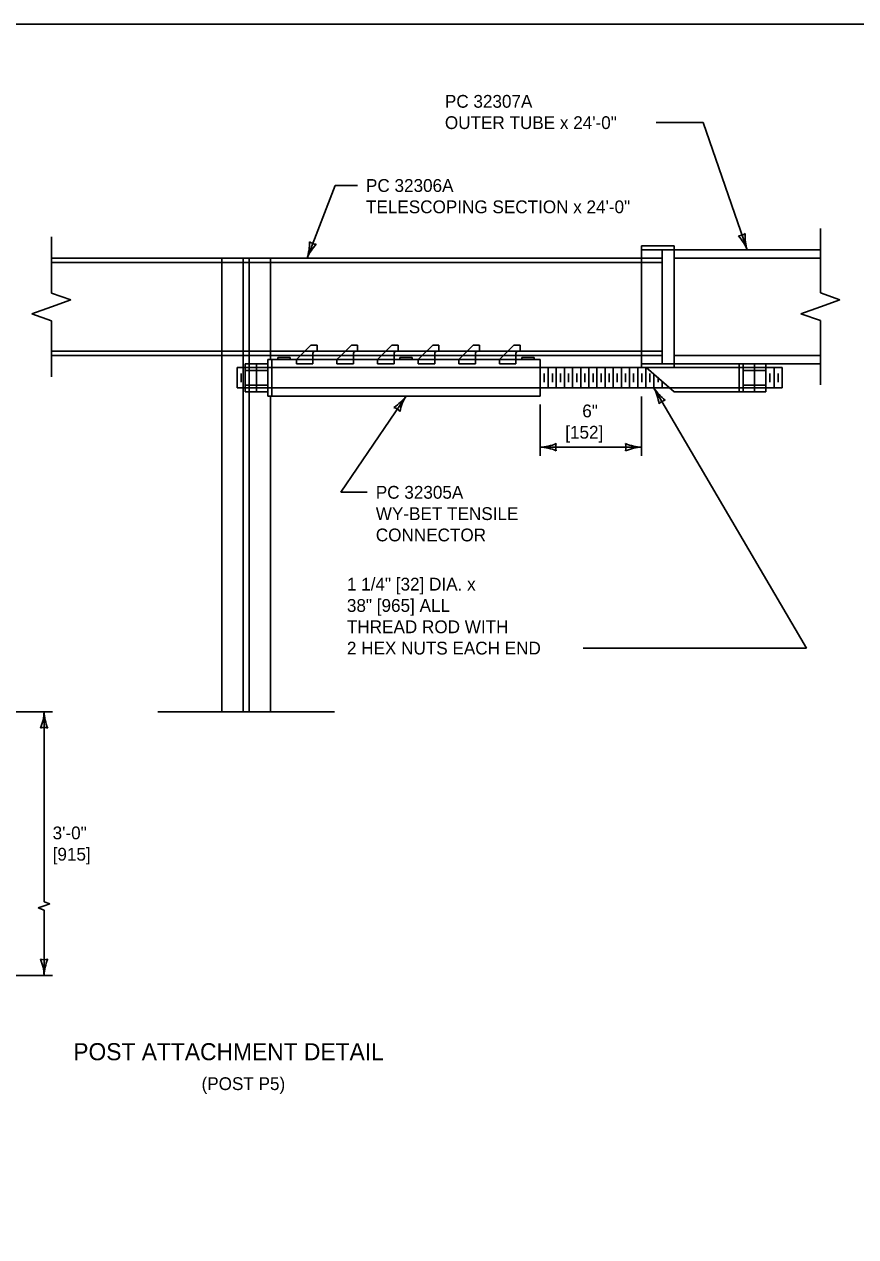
# Model space of a CAD drawing. Extents: x 49991.4 to 50021, y 49987.6 to 50011.4.
# Drawn here: x 50007.12 to 50011.02, y 49993.31 to 49999 of the extents above; entities that cross this region are included whole.
import ezdxf

# ---------------------------------------------------------------- set-up
doc = ezdxf.new("R2010")
doc.units = 0
for name, color, linetype in [('Level 1', 7, 'Continuous'), ('Level 2', 7, 'Continuous'), ('Level 3', 7, 'Continuous'), ('Level 4', 7, 'Continuous'), ('Level 6', 7, 'Continuous')]:
    doc.layers.add(name, color=color, linetype=linetype)

msp = doc.modelspace()

# ---------------------------------------------------------------- linework, layer by layer
at = {"layer": 'Level 1'}
for p, q in [((50010.0189, 49997.3882), (50010.0189, 49997.9592)), ((50010.1715, 49997.9592), (50010.0189, 49997.9592)), ((50010.1715, 49997.3882), (50010.1715, 49997.9592)), ((50007.2507, 49997.902), (50010.0189, 49997.902)), ((50010.8572, 49997.9405), (50010.1715, 49997.9405)), ((50007.2507, 49997.4448), (50010.0189, 49997.4448)), ((50008.0504, 49995.7737), (50008.0504, 49997.4448)), ((50008.2789, 49997.4261), (50008.2789, 49997.4448)), ((50008.3135, 49997.4261), (50008.3135, 49997.4361)), ((50008.3707, 49997.4361), (50008.3135, 49997.4361)), ((50008.3707, 49997.4261), (50008.3707, 49997.4361)), ((50008.4183, 49997.4448), (50008.3996, 49997.4261)), ((50008.477, 49997.4261), (50008.477, 49997.4448)), ((50008.6091, 49997.4448), (50008.5898, 49997.4261)), ((50008.6678, 49997.4261), (50008.6678, 49997.4448)), ((50008.7996, 49997.4448), (50008.7807, 49997.4261)), ((50008.858, 49997.4261), (50008.858, 49997.4448)), ((50008.8854, 49997.4261), (50008.8854, 49997.4361)), ((50008.9426, 49997.4361), (50008.8854, 49997.4361)), ((50008.9426, 49997.4261), (50008.9426, 49997.4361)), ((50008.9899, 49997.4448), (50008.9709, 49997.4261)), ((50009.0489, 49997.4261), (50009.0489, 49997.4448)), ((50009.1804, 49997.4448), (50009.1611, 49997.4261)), ((50009.2394, 49997.4261), (50009.2394, 49997.4448)), ((50009.3712, 49997.4448), (50009.3519, 49997.4261)), ((50009.4296, 49997.4261), (50009.4296, 49997.4448)), ((50009.5142, 49997.4361), (50009.457, 49997.4361)), ((50009.457, 49997.4261), (50009.457, 49997.4361)), ((50009.5142, 49997.4261), (50009.5142, 49997.4361)), ((50008.1215, 49997.3882), (50008.1597, 49997.3882)), ((50008.1215, 49997.2928), (50008.1215, 49997.3882)), ((50008.1597, 49997.2741), (50008.1597, 49997.4069)), ((50008.2663, 49997.4069), (50008.1597, 49997.4069)), ((50008.1597, 49997.3756), (50008.2663, 49997.3756)), ((50008.213, 49997.2741), (50008.213, 49997.4069)), ((50008.2663, 49997.4261), (50009.5425, 49997.4261)), ((50008.2663, 49997.2552), (50008.2663, 49997.4261)), ((50008.2852, 49997.2552), (50008.2852, 49997.4261)), ((50009.5425, 49997.2552), (50009.5425, 49997.4261)), ((50009.5425, 49997.3882), (50010.1715, 49997.3882)), ((50009.5807, 49997.2928), (50009.5807, 49997.3882)), ((50009.6186, 49997.2928), (50009.6186, 49997.3882)), ((50009.6571, 49997.2928), (50009.6571, 49997.3882)), ((50009.6954, 49997.2928), (50009.6954, 49997.3882)), ((50009.7333, 49997.2928), (50009.7333, 49997.3882)), ((50009.7712, 49997.2928), (50009.7712, 49997.3882)), ((50009.8094, 49997.2928), (50009.8094, 49997.3882)), ((50009.848, 49997.2928), (50009.848, 49997.3882)), ((50009.8856, 49997.2928), (50009.8856, 49997.3882)), ((50009.9238, 49997.2928), (50009.9238, 49997.3882)), ((50009.9617, 49997.2928), (50009.9617, 49997.3882)), ((50010.0006, 49997.2928), (50010.0006, 49997.3882)), ((50010.0385, 49997.2928), (50010.0385, 49997.3882)), ((50010.0403, 49997.3882), (50010.1715, 49997.2741)), ((50010.8572, 49997.4069), (50010.1715, 49997.4069)), ((50010.4758, 49997.2741), (50010.4758, 49997.4069)), ((50010.4951, 49997.2741), (50010.4951, 49997.4069)), ((50010.4951, 49997.3756), (50010.6016, 49997.3756)), ((50010.5484, 49997.2741), (50010.5484, 49997.4069)), ((50010.6016, 49997.2741), (50010.6016, 49997.4069)), ((50010.6016, 49997.3882), (50010.6775, 49997.3882)), ((50010.6399, 49997.2928), (50010.6399, 49997.3882)), ((50010.6775, 49997.2928), (50010.6775, 49997.3882)), ((50008.1414, 49997.3202), (50008.1414, 49997.3608)), ((50009.5617, 49997.3202), (50009.5617, 49997.3608)), ((50009.6003, 49997.3202), (50009.6003, 49997.3608)), ((50009.6379, 49997.3202), (50009.6379, 49997.3608)), ((50009.6758, 49997.3202), (50009.6758, 49997.3608)), ((50009.7146, 49997.3202), (50009.7146, 49997.3608)), ((50009.7523, 49997.3202), (50009.7523, 49997.3608)), ((50009.7908, 49997.3202), (50009.7908, 49997.3608)), ((50009.8287, 49997.3202), (50009.8287, 49997.3608)), ((50009.8669, 49997.3202), (50009.8669, 49997.3608)), ((50009.9046, 49997.3202), (50009.9046, 49997.3608)), ((50009.9434, 49997.3202), (50009.9434, 49997.3608)), ((50009.9813, 49997.3202), (50009.9813, 49997.3608)), ((50010.0195, 49997.3202), (50010.0195, 49997.3608)), ((50010.0572, 49997.3202), (50010.0572, 49997.3608)), ((50010.0767, 49997.2928), (50010.0767, 49997.3565)), ((50010.096, 49997.3202), (50010.096, 49997.3398)), ((50010.1149, 49997.2928), (50010.1149, 49997.3233)), ((50010.62, 49997.3202), (50010.62, 49997.3608)), ((50010.6591, 49997.3202), (50010.6591, 49997.3608)), ((50008.1597, 49997.2928), (50008.1215, 49997.2928)), ((50008.2663, 49997.306), (50008.1597, 49997.306)), ((50008.2663, 49997.2741), (50008.1597, 49997.2741)), ((50010.15, 49997.2928), (50009.5425, 49997.2928)), ((50010.6016, 49997.2741), (50010.1715, 49997.2741)), ((50010.6016, 49997.306), (50010.4951, 49997.306)), ((50010.6775, 49997.2928), (50010.6016, 49997.2928)), ((50008.2663, 49997.2552), (50009.5425, 49997.2552)), ((50008.2789, 49995.7737), (50008.2789, 49997.2552)), ((50004.756, 49995.7737), (50007.2567, 49995.7737)), ((50008.5789, 49995.7737), (50007.7504, 49995.7737))]:
    msp.add_line(p, q, dxfattribs=at)
msp.add_lwpolyline([(49999.3835, 49998.9992), (50016.7501, 49998.9992), (50016.7501, 49987.7988), (49999.3835, 49987.7988)], close=True, dxfattribs=at)
at = {"layer": 'Level 3'}
for p, q in [((50010.7922, 49996.0726), (50010.0767, 49997.2928)), ((50008.6084, 49996.8034), (50008.9139, 49997.2552)), ((50009.5425, 49997.2152), (50009.5425, 49996.9752)), ((50010.0189, 49997.2528), (50010.0189, 49996.9752)), ((50009.5425, 49997.0152), (50010.0189, 49997.0152)), ((50009.7445, 49996.0726), (50010.7922, 49996.0726)), ((50007.2441, 49994.8729), (50007.2167, 49994.8826)), ((50007.2441, 49994.8729), (50007.2167, 49994.8632)), ((50007.2167, 49994.8632), (50007.1893, 49994.8535)), ((50007.2167, 49994.8438), (50007.1893, 49994.8535))]:
    msp.add_line(p, q, dxfattribs=at)
for points in [[(50010.514, 49997.9405), (50010.3067, 49998.5376), (50010.0866, 49998.5376)], [(50008.5818, 49998.2427), (50008.4498, 49997.902)], [(50008.5818, 49998.2427), (50008.6862, 49998.2427)], [(50008.6084, 49996.8034), (50008.7322, 49996.8034)], [(50007.2167, 49995.7737), (50007.2167, 49994.8826)], [(50007.2167, 49994.8438), (50007.2167, 49994.5375)], [(50006.6689, 49994.5375), (50007.2567, 49994.5375)]]:
    msp.add_lwpolyline(points, dxfattribs=at)
for centre, radius, start, end in [((50010.4719, 49998.0616), 0.0548, 271.288, 307.0103), ((50010.2979, 49997.8533), 0.233, 21.9765, 41.2263), ((50010.7268, 49998.0047), 0.2223, 176.6052, 196.7887), ((50008.2286, 49997.9753), 0.233, 341.6554, 0.9053), ((50008.6536, 49997.8132), 0.2223, 136.2841, 156.4677), ((50008.4961, 49998.0216), 0.0548, 230.967, 266.6893), ((50009.8804, 49997.1883), 0.2223, 7.8448, 28.0283), ((50010.2716, 49997.4204), 0.233, 213.2161, 232.4659), ((50008.735, 49997.3872), 0.2223, 303.3901, 323.5736), ((50008.8421, 49997.149), 0.0548, 38.0729, 73.7952), ((50009.1131, 49997.1344), 0.233, 148.7614, 168.0112), ((50010.1415, 49997.1822), 0.0548, 102.5276, 138.2499), ((50009.531, 49997.2479), 0.233, 272.8273, 292.0772), ((50009.6707, 49997.0152), 0.0548, 162.1388, 197.8612), ((50010.028, 49997.2373), 0.2223, 247.456, 267.6395), ((50009.8907, 49997.0152), 0.0548, 342.1388, 17.8612), ((50009.5333, 49996.7931), 0.2223, 67.456, 87.6395), ((50010.0304, 49996.7825), 0.233, 92.8273, 112.0772), ((50006.9945, 49995.7829), 0.2223, 337.456, 357.6395), ((50007.4494, 49995.7852), 0.233, 182.8273, 202.0772), ((50007.2167, 49995.6455), 0.0548, 72.1388, 107.8612), ((50007.2167, 49994.6657), 0.0548, 252.1388, 287.8612), ((50006.984, 49994.526), 0.233, 2.8273, 22.0772), ((50007.4388, 49994.5283), 0.2223, 157.456, 177.6395)]:
    msp.add_arc(centre, radius, start, end, dxfattribs=at)
at = {"layer": 'Level 4'}
for p, q in [((50008.0504, 49997.4448), (50008.0504, 49997.902)), ((50008.1505, 49995.7737), (50008.1505, 49997.902)), ((50008.1789, 49995.7737), (50008.1789, 49997.902)), ((50008.2789, 49997.4448), (50008.2789, 49997.902)), ((50010.0189, 49997.9405), (50010.1715, 49997.9405)), ((50010.1153, 49997.902), (50010.0189, 49997.902)), ((50010.1153, 49997.4069), (50010.1153, 49997.9405)), ((50010.8572, 49997.902), (50010.1715, 49997.902)), ((50007.2507, 49997.8814), (50010.1153, 49997.8814)), ((50008.4673, 49997.4942), (50008.4183, 49997.4448)), ((50008.4965, 49997.4942), (50008.4673, 49997.4942)), ((50008.4965, 49997.465), (50008.4965, 49997.4942)), ((50008.6579, 49997.4942), (50008.6091, 49997.4448)), ((50008.6871, 49997.4942), (50008.6579, 49997.4942)), ((50008.6871, 49997.465), (50008.6871, 49997.4942)), ((50008.8481, 49997.4942), (50008.7996, 49997.4448)), ((50008.8776, 49997.4942), (50008.8481, 49997.4942)), ((50008.8776, 49997.465), (50008.8776, 49997.4942)), ((50009.0392, 49997.4942), (50008.9899, 49997.4448)), ((50009.0681, 49997.4942), (50009.0392, 49997.4942)), ((50009.0681, 49997.465), (50009.0681, 49997.4942)), ((50009.2291, 49997.4942), (50009.1804, 49997.4448)), ((50009.2583, 49997.4942), (50009.2291, 49997.4942)), ((50009.2583, 49997.465), (50009.2583, 49997.4942)), ((50009.42, 49997.4942), (50009.3712, 49997.4448)), ((50009.4489, 49997.4942), (50009.42, 49997.4942)), ((50009.4489, 49997.465), (50009.4489, 49997.4942)), ((50007.2507, 49997.4657), (50010.1153, 49997.4657)), ((50008.477, 49997.4448), (50008.477, 49997.4553)), ((50008.4965, 49997.465), (50008.4867, 49997.465)), ((50008.6678, 49997.4448), (50008.6678, 49997.4553)), ((50008.6871, 49997.465), (50008.6775, 49997.465)), ((50008.858, 49997.4448), (50008.858, 49997.4553)), ((50008.8776, 49997.465), (50008.8677, 49997.465)), ((50009.0489, 49997.4448), (50009.0489, 49997.4553)), ((50009.0681, 49997.465), (50009.0586, 49997.465)), ((50009.2394, 49997.4448), (50009.2394, 49997.4553)), ((50009.2583, 49997.465), (50009.2491, 49997.465)), ((50009.4296, 49997.4448), (50009.4296, 49997.4553)), ((50009.4489, 49997.465), (50009.4393, 49997.465)), ((50010.1153, 49997.4448), (50010.0189, 49997.4448)), ((50010.8572, 49997.4448), (50010.1715, 49997.4448)), ((50009.5425, 49997.3882), (50008.1597, 49997.3882)), ((50008.3996, 49997.4066), (50008.3996, 49997.4261)), ((50008.3996, 49997.4066), (50008.477, 49997.4066)), ((50008.477, 49997.4066), (50008.477, 49997.4261)), ((50008.5898, 49997.4066), (50008.5898, 49997.4261)), ((50008.5898, 49997.4066), (50008.6678, 49997.4066)), ((50008.6678, 49997.4066), (50008.6678, 49997.4261)), ((50008.7807, 49997.4066), (50008.7807, 49997.4261)), ((50008.7807, 49997.4066), (50008.858, 49997.4066)), ((50008.858, 49997.4066), (50008.858, 49997.4261)), ((50008.9709, 49997.4066), (50008.9709, 49997.4261)), ((50008.9709, 49997.4066), (50009.0489, 49997.4066)), ((50009.0489, 49997.4066), (50009.0489, 49997.4261)), ((50009.1611, 49997.4066), (50009.1611, 49997.4261)), ((50009.1611, 49997.4066), (50009.2394, 49997.4066)), ((50009.2394, 49997.4066), (50009.2394, 49997.4261)), ((50009.3519, 49997.4066), (50009.3519, 49997.4261)), ((50009.3519, 49997.4066), (50009.4296, 49997.4066)), ((50009.4296, 49997.4066), (50009.4296, 49997.4261)), ((50010.0189, 49997.4069), (50010.1715, 49997.4069)), ((50010.1715, 49997.3882), (50010.6016, 49997.3882)), ((50009.5425, 49997.2928), (50008.1597, 49997.2928)), ((50010.6016, 49997.2928), (50010.15, 49997.2928))]:
    msp.add_line(p, q, dxfattribs=at)
for centre in [(50008.4867, 49997.4553), (50008.6775, 49997.4553), (50008.8677, 49997.4553), (50009.0586, 49997.4553), (50009.2491, 49997.4553), (50009.4393, 49997.4553)]:
    msp.add_ellipse(centre, major_axis=(0, 0.00969), ratio=0.99999, start_param=0, end_param=1.570796, dxfattribs=at)
at = {"layer": 'Level 6'}
for p, q in [((50007.2507, 49997.7382), (50007.2507, 49998.002)), ((50010.8572, 49998.0405), (50010.8572, 49997.7385)), ((50007.3421, 49997.7058), (50007.2507, 49997.7382)), ((50010.9486, 49997.7061), (50010.8572, 49997.7385)), ((50007.2507, 49997.6734), (50007.1593, 49997.641)), ((50007.3421, 49997.7058), (50007.2507, 49997.6734)), ((50010.8572, 49997.6737), (50010.7658, 49997.6413)), ((50010.9486, 49997.7061), (50010.8572, 49997.6737)), ((50007.2507, 49997.6086), (50007.1593, 49997.641)), ((50007.2507, 49997.3448), (50007.2507, 49997.6086)), ((50010.8572, 49997.6089), (50010.7658, 49997.6413)), ((50010.8572, 49997.6089), (50010.8572, 49997.3069))]:
    msp.add_line(p, q, dxfattribs=at)

# ---------------------------------------------------------------- texts
at = {"layer": 'Level 2'}
for s, height, p in [('PC 32307A', 0.06, (50009.0962, 49998.6076)), ('OUTER TUBE x 24\'-0"', 0.06, (50009.0962, 49998.5076)), ('PC 32306A', 0.06, (50008.7262, 49998.2127)), ('TELESCOPING SECTION x 24\'-0"', 0.06, (50008.7262, 49998.1127)), ('6"', 0.06, (50009.7404, 49997.1552)), ('[152]', 0.06, (50009.6605, 49997.0552)), ('PC 32305A', 0.06, (50008.7722, 49996.7734)), ('WY-BET TENSILE', 0.06, (50008.7722, 49996.6734)), ('CONNECTOR', 0.06, (50008.7722, 49996.5734)), ('1 1/4" [32] DIA. x', 0.06, (50008.6367, 49996.3426)), ('38" [965] ALL', 0.06, (50008.6367, 49996.2426)), ('THREAD ROD WITH', 0.06, (50008.6367, 49996.1426)), ('2 HEX NUTS EACH END', 0.06, (50008.6367, 49996.0426)), ('3\'-0"', 0.06, (50007.2567, 49995.1756)), ('[915]', 0.06, (50007.2567, 49995.0756)), ('POST ATTACHMENT DETAIL', 0.08, (50007.3535, 49994.1393)), ('(POST P5)', 0.06, (50007.955, 49993.9993))]:
    msp.add_text(s, height=height, dxfattribs=at).set_placement(p)

doc.saveas('drawing.dxf')
